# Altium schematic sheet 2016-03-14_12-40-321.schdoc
size 285 x 119 mm; SheetNumber: 1; SheetTotal: 1
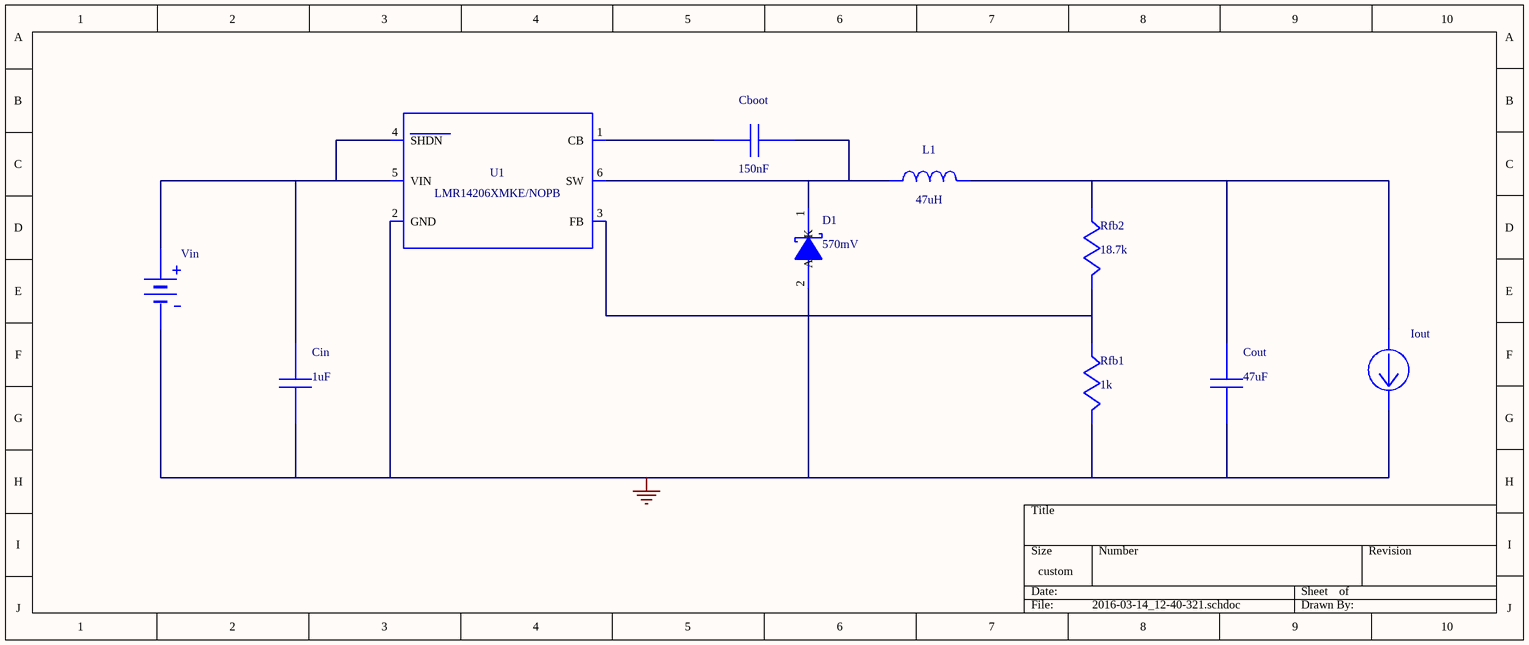
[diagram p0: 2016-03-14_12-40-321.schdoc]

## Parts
Cboot  value 150nF  (hidden comment: GRM155R61A154KE19D)
Cin  value 1uF  (hidden comment: GENERIC_CAPACITOR)
Cout  value 47uF  (hidden comment: C3216X5R1E476M160AC)
D1  value 570mV  (hidden comment: PMEG6010CEH,115)
Iout  WB_CURRENT_LOAD  (value not drawn)
L1  value 47uH  (hidden comment: SRN8040-470M)
Rfb1  value 1k  (hidden comment: CRCW04021K00FKED)
Rfb2  value 18.7k  (hidden comment: CRCW040218K7FKED)
U1  PackageReference: LMR14206XMKE/NOPB  (hidden comment: LMR14206XMK/NOPB)
Vin  WB_BATTERY  (value not drawn)

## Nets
0: Cin.2 Cout.2 D1.2(A) Iout.2(-) Rfb1.1 U1.2(GND) Vin.2(-)
NetCboot_1: Cboot.1 D1.1(K) L1.1 U1.6(SW)
NetCboot_2: Cboot.2 U1.1(CB)
NetCin_1: Cin.1 U1.4(SHDN) U1.5(VIN) Vin.1(+)
NetCout_1: Cout.1 Iout.1(+) L1.2 Rfb2.2
NetRfb1_2: Rfb1.2 Rfb2.1 U1.3(FB)

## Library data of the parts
Cboot = GRM155R61A154KE19D: GRM155R61A154KE1; Manufacturer Name: MuRata
Cin = GENERIC_CAPACITOR: C1608X7R1V105K08; Manufacturer Name: TDK
Cout = C3216X5R1E476M160AC: C3216X5R1E476M16; Manufacturer Name: TDK
D1 = PMEG6010CEH,115: Manufacturer Name: NXP Semiconductor
Iout = WB_CURRENT_LOAD: Value: UNLISTED
L1 = SRN8040-470M: Manufacturer Name: Bourns
Rfb1 = CRCW04021K00FKED: Manufacturer Name: Vishay-Dale
Rfb2 = CRCW040218K7FKED: Manufacturer Name: Vishay-Dale
U1 = LMR14206XMK/NOPB: LMR14206XMKE/NOP; Manufacturer Name: Texas Instruments; Value: UNLISTED
Vin = WB_BATTERY: Value: UNLISTED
